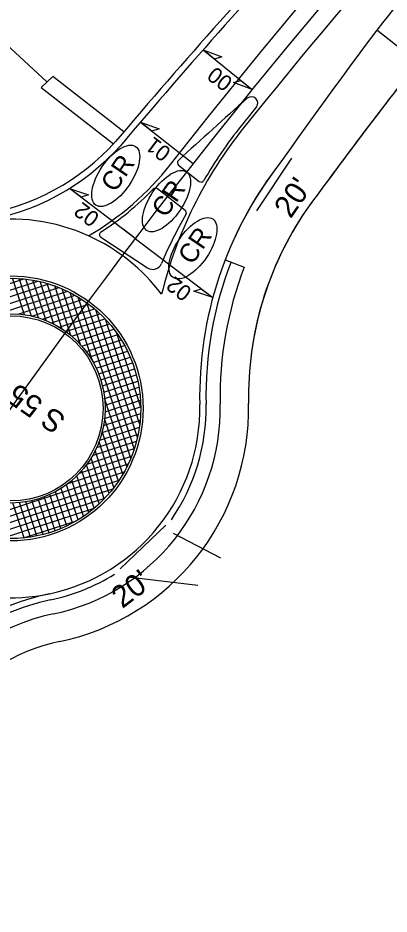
# Model space of a CAD drawing. Extents: x 1974386 to 1979988, y 776712 to 784860.
# Drawn here: x 1976378 to 1976495.8, y 779314.9 to 779598.9 of the extents above; entities that cross this region are included whole.
import ezdxf

# ---------------------------------------------------------------- set-up
doc = ezdxf.new("R2010")
doc.units = 0
for name, color, linetype in [('Prop Conc 12in Island Cover', 7, 'Continuous'), ('Prop Conc 1ft 6in Curb and Gutter', 7, 'Continuous'), ('Prop Conc 2ft 6in Curb and Gutter', 7, 'Continuous'), ('Prop Conc 4in Sidewalk', 7, 'Continuous'), ('Prop Conc 5in Monolithic Keyed In Island', 7, 'Continuous'), ('Prop Conc Curb 8in x 18in', 7, 'Continuous'), ('Prop Conc Drive Drop Type', 7, 'Continuous'), ('Prop Dimension', 7, 'Continuous'), ('Prop EOT', 7, 'Continuous'), ('Prop Horizontal Alignment', 7, 'Continuous'), ('Prop Horizontal Alignment Direction Label', 7, 'Continuous'), ('Prop Horizontal Alignment Tick Small', 7, 'Continuous'), ('Prop Lane Lines', 7, 'Continuous'), ('Prop Superelevation  Arrow CELL', 7, 'Continuous'), ('Prop Superelevation Label', 7, 'Continuous'), ('Prop WCC CELL', 7, 'Continuous')]:
    doc.layers.add(name, color=color, linetype=linetype)

msp = doc.modelspace()

# ---------------------------------------------------------------- linework, layer by layer
at = {"layer": 'Prop Conc 12in Island Cover'}
for p, q in [((1976342.67, 779499.76), (1976387.91, 779514.55)), ((1976345.01, 779502.63), (1976384.32, 779515.48)), ((1976348.12, 779505.75), (1976379.97, 779516.17)), ((1976380.09, 779504.8), (1976376.31, 779516.38)), ((1976382.33, 779504.39), (1976378.44, 779516.3)), ((1976384.63, 779503.78), (1976380.61, 779516.1)), ((1976387.01, 779502.94), (1976382.82, 779515.77)), ((1976389.49, 779501.79), (1976385.07, 779515.32)), ((1976392.09, 779500.27), (1976387.37, 779514.71)), ((1976394.85, 779498.26), (1976389.73, 779513.95)), ((1976340.81, 779497.05), (1976391.01, 779513.46)), ((1976370.49, 779504.65), (1976393.75, 779512.25)), ((1976378.08, 779505.03), (1976396.21, 779510.96)), ((1976397.91, 779495.36), (1976392.14, 779512.99)), ((1976401.7, 779490.2), (1976394.63, 779511.81)), ((1976382.47, 779504.36), (1976398.45, 779509.58)), ((1976385.86, 779503.36), (1976400.49, 779508.15)), ((1976413.88, 779459.37), (1976397.21, 779510.37)), ((1976414.99, 779462.4), (1976399.9, 779508.58)), ((1976388.7, 779502.19), (1976402.37, 779506.65)), ((1976415.96, 779465.89), (1976402.73, 779506.34)), ((1976391.14, 779500.88), (1976404.09, 779505.11)), ((1976393.27, 779499.47), (1976405.68, 779503.53)), ((1976416.7, 779470.07), (1976405.8, 779503.4)), ((1976395.16, 779497.99), (1976407.14, 779501.9)), ((1976396.85, 779496.44), (1976408.49, 779500.24)), ((1976398.36, 779494.83), (1976409.72, 779498.54)), ((1976399.71, 779493.16), (1976410.86, 779496.81)), ((1976417.01, 779475.56), (1976409.29, 779499.16)), ((1976400.91, 779491.45), (1976411.89, 779495.04)), ((1976401.97, 779489.69), (1976412.82, 779493.24)), ((1976402.9, 779487.89), (1976413.66, 779491.41)), ((1976403.7, 779486.05), (1976414.41, 779489.55)), ((1976404.37, 779484.16), (1976415.06, 779487.66)), ((1976404.9, 779482.23), (1976415.62, 779485.74)), ((1976405.31, 779480.26), (1976416.09, 779483.79)), ((1976405.58, 779478.25), (1976416.46, 779481.81)), ((1976405.72, 779476.19), (1976416.74, 779479.79)), ((1976412.65, 779456.69), (1976405.57, 779478.36)), ((1976405.72, 779474.09), (1976416.93, 779477.75)), ((1976405.57, 779471.93), (1976417, 779475.67)), ((1976404.74, 779467.45), (1976416.84, 779471.41)), ((1976405.25, 779469.72), (1976416.98, 779473.56)), ((1976411.34, 779454.27), (1976405.57, 779471.93)), ((1976404.02, 779465.11), (1976416.58, 779469.22)), ((1976403.05, 779462.69), (1976416.2, 779466.99)), ((1976409.96, 779452.07), (1976404.82, 779467.77)), ((1976401.73, 779460.16), (1976415.67, 779464.71)), ((1976408.51, 779450.06), (1976403.79, 779464.48)), ((1976397.6, 779454.6), (1976414.13, 779460)), ((1976400, 779457.49), (1976414.99, 779462.39)), ((1976407.01, 779448.21), (1976402.58, 779461.75)), ((1976393.96, 779451.3), (1976413.07, 779457.55)), ((1976403.87, 779444.94), (1976399.84, 779457.26)), ((1976405.46, 779446.51), (1976401.26, 779459.36)), ((1976358.58, 779437.63), (1976411.77, 779455.02)), ((1976402.24, 779443.5), (1976398.35, 779455.39)), ((1976361.42, 779436.46), (1976410.18, 779452.4)), ((1976398.86, 779440.96), (1976395.16, 779452.26)), ((1976400.56, 779442.18), (1976396.78, 779453.74)), ((1976364.65, 779435.41), (1976408.19, 779449.64)), ((1976393.54, 779437.91), (1976390, 779448.74)), ((1976395.35, 779438.83), (1976391.77, 779449.77)), ((1976397.12, 779439.84), (1976393.49, 779450.94)), ((1976368.43, 779434.54), (1976405.65, 779446.71)), ((1976384.06, 779434.73), (1976380.53, 779445.53)), ((1976386.02, 779435.18), (1976382.51, 779445.92)), ((1976387.94, 779435.72), (1976384.44, 779446.44)), ((1976389.84, 779436.36), (1976386.34, 779447.08)), ((1976391.71, 779437.09), (1976388.19, 779447.84)), ((1976373.12, 779433.97), (1976402.21, 779443.48)), ((1976380.06, 779434.11), (1976376.44, 779445.16)), ((1976382.08, 779434.37), (1976378.51, 779445.28)), ((1976379.95, 779434.1), (1976396.62, 779439.55))]:
    msp.add_line(p, q, dxfattribs=at)
msp.add_circle((1976375.76, 779475.13), 30, dxfattribs=at)
at = {"layer": 'Prop Conc 1ft 6in Curb and Gutter'}
msp.add_circle((1976375.76, 779475.13), 41.25, dxfattribs=at)
at = {"layer": 'Prop Conc 2ft 6in Curb and Gutter'}
for centre, radius, start, end in [((1977876.35, 778316.74), 1922.99, 136.72119, 139.7323), ((1976354.76, 779608.49), 73, 278.9494, 318.0674), ((1976555.72, 779478.88), 118, 158.8164, 181.1936), ((1976375.76, 779475.13), 62, 325.3321, 1.1936), ((1976375.76, 779475.13), 62, 281.7976, 302.0681), ((1976403.36, 779342.98), 73, 101.7976, 147.0235)]:
    msp.add_arc(centre, radius, start, end, dxfattribs=at)
at = {"layer": 'Prop Conc 4in Sidewalk'}
for p, q in [((1976389.12, 779580.28), (1976385.41, 779576.84)), ((1976411.63, 779562.73), (1976389.12, 779580.28)), ((1976385.41, 779576.84), (1976408.36, 779558.94)), ((1976443.83, 779522.25), (1976449.89, 779519.9)), ((1976443.83, 779522.25), (1976449.89, 779519.9))]:
    msp.add_line(p, q, dxfattribs=at)
msp.add_lwpolyline([(1976500.96, 779587.88), (1976495.85, 779591.9), (1976491.91, 779594.98)], dxfattribs=at)
for centre, radius, start, end in [((1977998.02, 778464.91), 1882.93, 143.11825, 144.71902), ((1977976.01, 778435.99), 1866.53, 142.01244, 143.82111), ((1977976.36, 778436.41), 1866.55, 142.02902, 143.82111), ((1976555.72, 779478.88), 120, 142.1787, 158.8164), ((1976555.72, 779478.88), 104.5, 145.3825, 181.1936), ((1976555.72, 779478.88), 104.5, 145.6777, 181.1936), ((1976555.72, 779478.88), 113.5, 158.8164, 181.1936), ((1976555.72, 779478.88), 113.5, 158.8164, 181.1936), ((1976375.76, 779475.13), 66.5, 281.7976, 1.1936), ((1976375.76, 779475.13), 66.5, 281.7976, 1.1936), ((1976375.76, 779475.13), 75.5, 281.7976, 1.1936), ((1976375.76, 779475.13), 75.5, 281.7976, 1.1936), ((1976403.36, 779342.98), 68.5, 101.7976, 147.0235), ((1976403.36, 779342.98), 68.5, 101.7976, 147.0235), ((1976403.36, 779342.98), 59.5, 101.7976, 143.2714), ((1976403.36, 779342.98), 59.5, 101.7976, 143.2714)]:
    msp.add_arc(centre, radius, start, end, dxfattribs=at)
at = {"layer": 'Prop Conc 5in Monolithic Keyed In Island'}
msp.add_line((1976404.41, 779529.36), (1976419.19, 779519.66), dxfattribs=at)
for points in [[(1976429.02, 779552.19), (1976435.57, 779547.06)], [(1976431.12, 779537.88), (1976422.31, 779544.72)], [(1976404.41, 779529.36), (1976419.19, 779519.66)]]:
    msp.add_lwpolyline(points, dxfattribs=at)
for centre, radius, start, end in [((1977729.61, 778130.27), 1928.18, 131.54456, 132.41906), ((1977729.61, 778130.27), 1928.18, 131.54456, 132.41906), ((1976452.17, 779571.9), 2, 321.0068, 131.5446), ((1976452.17, 779571.9), 2, 321.0068, 131.5446), ((1977926.94, 778377.94), 1895.5, 141.00683, 141.23948), ((1977926.94, 778377.94), 1895.5, 141.00683, 141.23948), ((1976555.72, 779478.88), 137, 141.2395, 150.018), ((1976555.72, 779478.88), 137, 141.2395, 150.018), ((1976429.64, 779552.98), 1, 132.4191, 231.9065), ((1976429.64, 779552.98), 1, 132.4191, 231.9065), ((1976421.7, 779543.93), 1, 52.2081, 136.0364), ((1976421.7, 779543.93), 1, 52.2081, 136.0364), ((1976436.19, 779547.84), 1, 231.9065, 330.018), ((1976436.19, 779547.84), 1, 231.9065, 330.018), ((1976354.76, 779608.49), 92, 302.6674, 316.0364), ((1976354.76, 779608.49), 92, 302.6674, 316.0364), ((1976548.77, 779468.25), 135.84, 149.792, 157.1435), ((1976548.77, 779468.25), 135.84, 149.792, 157.1435), ((1976430.51, 779537.09), 1, 329.792, 52.2081), ((1976430.51, 779537.09), 1, 329.792, 52.2081), ((1976404.95, 779530.2), 1, 122.6674, 236.722), ((1976404.95, 779530.2), 1, 122.6674, 236.722), ((1976420.83, 779522.17), 3, 236.722, 337.1435), ((1976420.83, 779522.17), 3, 236.722, 337.1435)]:
    msp.add_arc(centre, radius, start, end, dxfattribs=at)
at = {"layer": 'Prop Conc Curb 8in x 18in'}
msp.add_circle((1976375.76, 779475.13), 29.33, dxfattribs=at)
at = {"layer": 'Prop Conc Drive Drop Type'}
for p, q in [((1976464.91, 779554.4), (1976453.77, 779537.7)), ((1976424.94, 779438.14), (1976410.48, 779424.32))]:
    msp.add_line(p, q, dxfattribs=at)
at = {"layer": 'Prop Dimension'}
msp.add_line((1976387.27, 779578.56), (1976374.32, 779590.53), dxfattribs=at)
at = {"layer": 'Prop EOT'}
for p, q in [((1976427.36, 779435.61), (1976442.3, 779427.75)), ((1976412.9, 779421.79), (1976435.19, 779419.09))]:
    msp.add_line(p, q, dxfattribs=at)
msp.add_circle((1976375.76, 779475.13), 42, dxfattribs=at)
for centre, radius, start, end in [((1977876.35, 778316.74), 1920.99, 136.7176, 139.73317), ((1977993.01, 778468.56), 1876.73, 143.11561, 144.72166), ((1976354.76, 779608.49), 75, 278.9494, 318.0674), ((1976555.72, 779478.88), 120, 142.1787, 181.1936), ((1976375.76, 779475.13), 60, 281.7976, 1.1936), ((1976403.36, 779342.98), 75, 101.7976, 147.0005)]:
    msp.add_arc(centre, radius, start, end, dxfattribs=at)
at = {"layer": 'Prop Horizontal Alignment'}
msp.add_arc((1977926.94, 778377.94), 1900, 135.73946, 152.1381, dxfattribs=at)
at = {"layer": 'Prop Horizontal Alignment Tick Small'}
msp.add_line((1976415.27, 779528.97), (1976411.3, 779532), dxfattribs=at)
at = {"layer": 'Prop Lane Lines'}
for centre, radius, start, end in [((1977926.94, 778377.94), 1905.5, 135.73946, 141.94983), ((1977926.94, 778377.94), 1894.5, 135.73946, 141.23948), ((1977976.01, 778435.99), 1883.03, 140.59771, 142.01248), ((1976555.72, 779478.88), 136, 141.2395, 166.2129), ((1976354.76, 779608.49), 91, 300.1571, 321.9498), ((1976375.76, 779475.13), 60, 65.6747, 98.9494), ((1976375.76, 779475.13), 60, 37.0615, 65.6747), ((1976375.76, 779475.13), 60, 248.5228, 281.7976)]:
    msp.add_arc(centre, radius, start, end, dxfattribs=at)
at = {"layer": 'Prop Superelevation  Arrow CELL'}
for p, q in [((1976436.83, 779588.75), (1976452.37, 779576.12)), ((1976416.92, 779565.84), (1976433.64, 779552.69)), ((1976415.27, 779528.97), (1976394.43, 779544.84)), ((1976415.27, 779528.97), (1976439.88, 779510.23))]:
    msp.add_line(p, q, dxfattribs=at)
for points in [[(1976436.83, 779588.75), (1976442.75, 779586.51), (1976440.42, 779585.83)], [(1976452.37, 779576.12), (1976446.45, 779578.35), (1976448.78, 779579.04)], [(1976416.92, 779565.84), (1976422.87, 779563.71), (1976420.55, 779562.98)], [(1976394.43, 779544.84), (1976400.41, 779542.8), (1976398.11, 779542.04)], [(1976439.88, 779510.23), (1976433.9, 779512.27), (1976436.21, 779513.03)]]:
    msp.add_lwpolyline(points, close=True, dxfattribs=at)
at = {"layer": 'Prop WCC CELL'}
for centre in [(1976409.08, 779548.82), (1976425.2, 779540.8), (1976433.58, 779525.87)]:
    msp.add_ellipse(centre, major_axis=(6.3, 9.28), ratio=0.462467, dxfattribs=at)

# ---------------------------------------------------------------- texts
at = {"layer": 'Prop Horizontal Alignment Direction Label'}
msp.add_text('S 55%%d 10\' 36.6" E', height=7, rotation=145.1768, dxfattribs=at).set_placement((1976393.74, 779472.38))
at = {"layer": 'Prop Superelevation  Arrow CELL'}
for rotation, p in [(55.2849, (1976464.58, 779535)), (37.5305, (1976411.19, 779411.52))]:
    msp.add_text("20'", height=7, rotation=rotation, dxfattribs=at).set_placement(p)
at = {"layer": 'Prop Superelevation Label'}
for s, p in [('00', (1976446.58, 779579.21)), ('01', (1976427, 779556.93)), ('02', (1976404.3, 779536.25)), ('02', (1976433.6, 779512.71))]:
    msp.add_text(s, height=5, rotation=142.7135, dxfattribs=at).set_placement(p)
at = {"layer": 'Prop WCC CELL'}
for p in [(1976408.88, 779543.27), (1976425, 779535.24), (1976433.38, 779520.31)]:
    msp.add_text('CR', height=6, rotation=55.8441, dxfattribs=at).set_placement(p)

doc.saveas('drawing.dxf')
